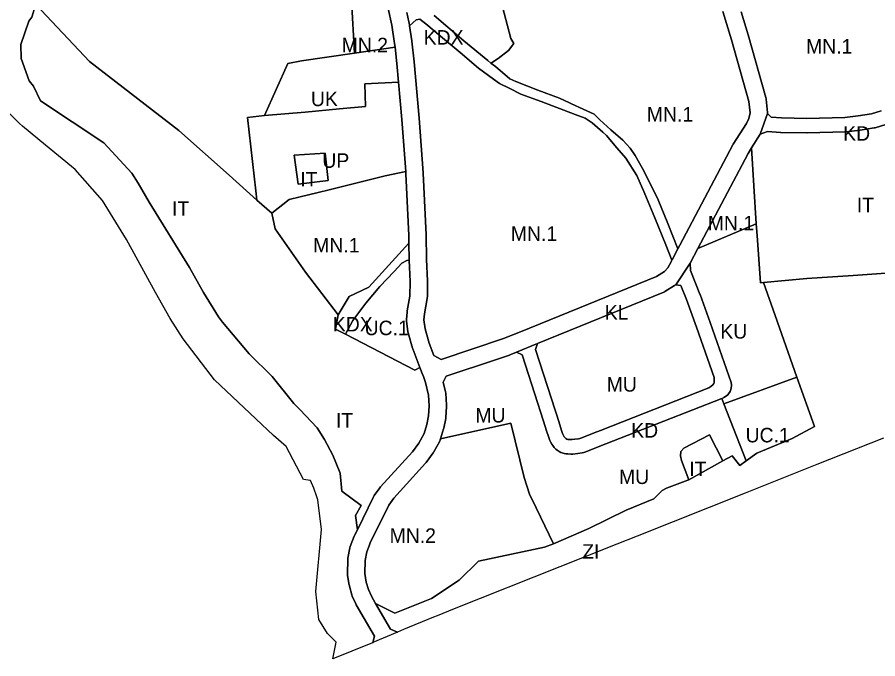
# Model space of a CAD drawing. Extents: x 7431767 to 7433133, y 5549450 to 5550702.
# Drawn here: x 7432225 to 7432819, y 5549450 to 5549893 of the extents above; entities that cross this region are included whole.
import ezdxf

# ---------------------------------------------------------------- set-up
doc = ezdxf.new("R2010")
doc.units = 0
doc.layers.add('linie_rozgraniczajace', color=7, linetype='Continuous')
doc.layers.add('oznaczenia_przeznaczen', color=7, linetype='Continuous')

msp = doc.modelspace()

# ---------------------------------------------------------------- linework, layer by layer
at = {"layer": 'linie_rozgraniczajace'}
for points in [[(7432557.4, 5549908.99), (7432565.41, 5549878.06), (7432567.36, 5549874.65), (7432563.8, 5549869.83), (7432556.62, 5549864.24), (7432552.14, 5549861.46), (7432551.68, 5549861.15), (7432549.45, 5549862.88), (7432532.98, 5549876.47), (7432512.5, 5549894.02)], [(7432711.61, 5549896.7), (7432717.56, 5549877.14), (7432729.67, 5549834.62), (7432730.42, 5549826.81), (7432729.64, 5549822.98), (7432727.85, 5549819.49), (7432718.76, 5549805.14), (7432718.65, 5549804.9), (7432718.53, 5549804.74), (7432681.99, 5549735.62), (7432680.66, 5549733.08), (7432673.64, 5549750.42), (7432667.12, 5549766.8), (7432659.94, 5549781.24), (7432656.21, 5549788.37), (7432651.18, 5549797.53), (7432647.66, 5549802.42), (7432642.59, 5549807.97), (7432634.3, 5549815.05), (7432626.88, 5549822.03), (7432622.88, 5549825.97), (7432617.72, 5549828.25), (7432615.3, 5549829.33), (7432607.27, 5549832.99), (7432605.87, 5549833.66), (7432599.04, 5549836.95), (7432584.12, 5549842.44), (7432568.93, 5549848.41), (7432564.81, 5549850.43), (7432554.78, 5549858.73), (7432551.68, 5549861.15), (7432552.14, 5549861.46), (7432556.62, 5549864.24), (7432563.8, 5549869.83), (7432567.36, 5549874.65), (7432565.41, 5549878.06), (7432557.4, 5549908.99)], [(7432455.58, 5549904.25), (7432457.52, 5549868.02), (7432421.02, 5549862.63), (7432411.67, 5549860.97), (7432395.56, 5549824.94), (7432383.73, 5549823.62), (7432389.41, 5549773.01), (7432390.29, 5549766.69), (7432371.05, 5549783.92), (7432336.34, 5549814.7), (7432274.77, 5549862.2), (7432237.84, 5549901.52)], [(7432237.84, 5549901.52), (7432274.77, 5549862.2), (7432336.34, 5549814.7), (7432371.05, 5549783.92), (7432390.29, 5549766.69), (7432400.61, 5549757.58), (7432402.86, 5549746.86), (7432423.86, 5549717), (7432446.24, 5549687.41), (7432444.54, 5549677.59), (7432451.31, 5549674.09), (7432499.26, 5549649.31), (7432502.63, 5549651.09), (7432504.59, 5549645.96), (7432504.82, 5549645.62), (7432506.45, 5549640.91), (7432508.56, 5549632.01), (7432509.11, 5549624.74), (7432508.63, 5549617.9), (7432507.41, 5549611.95), (7432505.51, 5549605.59), (7432501.9, 5549598.93), (7432497.55, 5549592.91), (7432475.54, 5549568.76), (7432475.12, 5549568.24), (7432471.24, 5549562.89), (7432470.98, 5549562.41), (7432470.72, 5549562.01), (7432459.54, 5549539.23), (7432458.32, 5549549.15), (7432462.08, 5549556.07), (7432448.76, 5549565.92), (7432447.6, 5549578.37), (7432442.66, 5549590.67), (7432436.94, 5549601.45), (7432431.82, 5549609.5), (7432419.86, 5549622.15), (7432415.69, 5549626.43), (7432400.74, 5549644.89), (7432384.84, 5549660.55), (7432366.47, 5549682.47), (7432363.79, 5549686.18), (7432353.38, 5549702.91), (7432343.77, 5549720.1), (7432315.99, 5549765.15), (7432308.26, 5549778.4), (7432304.07, 5549785.22), (7432284.58, 5549806.24), (7432240.93, 5549835.19), (7432236.06, 5549845.16), (7432233.16, 5549848.85), (7432227.68, 5549864.31), (7432227.29, 5549874.03), (7432232.98, 5549890.15), (7432235, 5549892.77), (7432237.51, 5549901.14)], [(7432237.51, 5549901.14), (7432235, 5549892.77), (7432232.98, 5549890.15), (7432227.29, 5549874.03), (7432227.68, 5549864.31), (7432233.16, 5549848.85), (7432236.06, 5549845.16), (7432240.93, 5549835.19), (7432284.58, 5549806.24), (7432304.07, 5549785.22), (7432308.26, 5549778.4), (7432315.99, 5549765.15), (7432343.77, 5549720.1), (7432353.38, 5549702.91), (7432363.79, 5549686.18), (7432366.47, 5549682.47), (7432384.84, 5549660.55), (7432400.74, 5549644.89), (7432415.69, 5549626.43), (7432419.86, 5549622.15), (7432431.82, 5549609.5), (7432436.94, 5549601.45), (7432442.66, 5549590.67), (7432447.6, 5549578.37), (7432448.76, 5549565.92), (7432462.08, 5549556.07), (7432458.32, 5549549.15), (7432459.54, 5549539.23)], [(7432520.6, 5549616.69), (7432520.52, 5549616.35), (7432520.48, 5549615.87), (7432519.12, 5549609.26), (7432518.98, 5549608.84), (7432516.94, 5549601.99), (7432516.8, 5549601.55), (7432516.72, 5549601.41), (7432516.69, 5549601.21), (7432516.35, 5549600.43), (7432512.28, 5549592.89), (7432512.04, 5549592.54), (7432511.87, 5549592.22), (7432507.07, 5549585.61), (7432506.65, 5549585.09), (7432484.65, 5549560.93), (7432481.24, 5549556.27), (7432468.47, 5549530.19), (7432467.65, 5549528.11), (7432466.04, 5549524), (7432464.88, 5549517.9), (7432464.76, 5549509.1), (7432465.72, 5549503.14), (7432467.12, 5549497.95), (7432469.19, 5549493.32), (7432472.08, 5549488.38), (7432482.46, 5549470.75), (7432487.23, 5549468.61), (7432470.24, 5549461.33), (7432471.43, 5549465.82), (7432458.7, 5549487.52), (7432458.39, 5549488.11), (7432455.95, 5549493.52), (7432455.67, 5549494.36), (7432454.05, 5549500.31), (7432454, 5549500.67), (7432453.93, 5549500.92), (7432452.81, 5549507.71), (7432452.75, 5549508.42), (7432452.77, 5549508.6), (7432452.74, 5549508.75), (7432452.9, 5549518.59), (7432452.95, 5549518.85), (7432452.98, 5549519.61), (7432454.35, 5549526.78), (7432454.63, 5549527.73), (7432457.4, 5549534.83), (7432457.57, 5549535.25), (7432459.54, 5549539.23), (7432470.72, 5549562.01), (7432470.98, 5549562.41), (7432471.24, 5549562.89), (7432475.12, 5549568.24), (7432475.54, 5549568.76), (7432497.55, 5549592.91), (7432501.9, 5549598.93), (7432505.51, 5549605.59), (7432507.41, 5549611.95), (7432508.63, 5549617.9), (7432509.11, 5549624.74), (7432508.56, 5549632.01), (7432506.45, 5549640.91), (7432504.82, 5549645.62), (7432504.59, 5549645.96), (7432502.63, 5549651.09), (7432497.73, 5549663.97), (7432497.55, 5549664.45), (7432494.52, 5549675.12), (7432494.43, 5549675.75), (7432494.33, 5549676.06), (7432493.51, 5549683.13), (7432493.53, 5549683.34), (7432493.46, 5549683.59), (7432493.47, 5549684.22), (7432493.82, 5549689.42), (7432493.87, 5549689.7), (7432493.91, 5549690.15), (7432495.81, 5549700.36), (7432495.93, 5549710.61), (7432495.34, 5549725.17), (7432495.33, 5549725.34), (7432495.14, 5549736.87), (7432495.05, 5549742.32), (7432493.05, 5549784.68), (7432492.92, 5549786.29), (7432490.18, 5549822.16), (7432487.94, 5549848.01), (7432486.83, 5549860.84), (7432485.5, 5549872.15), (7432485.17, 5549874.8), (7432483.35, 5549887.26), (7432480.75, 5549898.9)], [(7432493.66, 5549896.09), (7432495.11, 5549889.67), (7432495.15, 5549889.38), (7432495.18, 5549889.24), (7432495.53, 5549886.93), (7432497.08, 5549876.47), (7432497.08, 5549876.33), (7432498.75, 5549862.15), (7432498.76, 5549861.96), (7432502.12, 5549823.16), (7432505.02, 5549785.52), (7432505.03, 5549785.34), (7432507.04, 5549742.79), (7432507.05, 5549742.61), (7432507.33, 5549725.61), (7432507.92, 5549710.95), (7432507.9, 5549710.79), (7432507.94, 5549710.65), (7432507.82, 5549699.72), (7432507.76, 5549699.48), (7432507.7, 5549698.67), (7432505.75, 5549688.29), (7432505.48, 5549683.99), (7432506.2, 5549677.94), (7432509.01, 5549667.97), (7432512.3, 5549659.34), (7432517.28, 5549656.75), (7432560.45, 5549671.08), (7432572.18, 5549675.86), (7432665.85, 5549714.06), (7432671.41, 5549717.47), (7432673.71, 5549719.98), (7432675.89, 5549724.11), (7432676.21, 5549724.72), (7432676.47, 5549725.2), (7432676.59, 5549725.43), (7432680.66, 5549733.08), (7432681.99, 5549735.62), (7432718.53, 5549804.74), (7432718.65, 5549804.9), (7432718.76, 5549805.14), (7432727.85, 5549819.49), (7432729.64, 5549822.98), (7432730.42, 5549826.81), (7432729.67, 5549834.62), (7432717.56, 5549877.14), (7432711.61, 5549896.7)], [(7432512.5, 5549894.02), (7432532.98, 5549876.47), (7432549.45, 5549862.88), (7432551.68, 5549861.15), (7432554.78, 5549858.73), (7432564.81, 5549850.43), (7432568.93, 5549848.41), (7432584.12, 5549842.44), (7432599.04, 5549836.95), (7432605.87, 5549833.66), (7432607.27, 5549832.99), (7432615.3, 5549829.33), (7432617.72, 5549828.25), (7432622.88, 5549825.97), (7432626.88, 5549822.03), (7432634.3, 5549815.05), (7432642.59, 5549807.97), (7432647.66, 5549802.42), (7432651.18, 5549797.53), (7432656.21, 5549788.37), (7432659.94, 5549781.24), (7432667.12, 5549766.8), (7432673.64, 5549750.42), (7432680.66, 5549733.08), (7432676.59, 5549725.43), (7432676.47, 5549725.2), (7432672.38, 5549735.87), (7432664.78, 5549754.4), (7432657.92, 5549770.9), (7432652.27, 5549783.68), (7432644.66, 5549795.52), (7432638.48, 5549802.81), (7432631.45, 5549811.27), (7432628.89, 5549813.51), (7432621.53, 5549819.9), (7432616.58, 5549823.27), (7432609.78, 5549825.71), (7432586.43, 5549834.75), (7432572.19, 5549839.79), (7432564.68, 5549843.74), (7432557.66, 5549847.06), (7432553.51, 5549850.02), (7432543.19, 5549857.68), (7432530.37, 5549868.46), (7432516.96, 5549879.76), (7432506.77, 5549888.18), (7432502.54, 5549891.42), (7432500.15, 5549891.02), (7432495.53, 5549886.93), (7432495.18, 5549889.24), (7432495.15, 5549889.38), (7432495.11, 5549889.67), (7432493.66, 5549896.09)], [(7432724.22, 5549896.44), (7432729.06, 5549880.57), (7432741.35, 5549837.39), (7432741.47, 5549836.62), (7432741.55, 5549836.34), (7432742.45, 5549827.09), (7432742.43, 5549826.92), (7432742.5, 5549826.74), (7432742.48, 5549826.44), (7432737.37, 5549812.09), (7432731.37, 5549802.63), (7432729.02, 5549798.92), (7432694.32, 5549733.25), (7432689, 5549723.21), (7432679.13, 5549708.26), (7432678.4, 5549707.68), (7432671.72, 5549703.58), (7432671.11, 5549703.25), (7432670.95, 5549703.21), (7432583.74, 5549667.61), (7432569.4, 5549661.74), (7432568.88, 5549661.56), (7432564.82, 5549659.9), (7432564.42, 5549659.76), (7432554.73, 5549656.54), (7432520.75, 5549645.27), (7432518.73, 5549641.12), (7432520.35, 5549634.32), (7432520.45, 5549633.51), (7432520.49, 5549633.38), (7432521.1, 5549625.2), (7432521.11, 5549625), (7432521.1, 5549624.36), (7432520.6, 5549616.69)], [(7432820.96, 5549828.3), (7432814.2, 5549826.27), (7432804.93, 5549824.88), (7432795.76, 5549823.69), (7432769.67, 5549823.05), (7432752.11, 5549823.38), (7432744.96, 5549823.9), (7432742.48, 5549826.44), (7432742.5, 5549826.74), (7432742.43, 5549826.92), (7432742.45, 5549827.09), (7432741.55, 5549836.34), (7432741.47, 5549836.62), (7432741.35, 5549837.39), (7432729.06, 5549880.57), (7432724.22, 5549896.44)], [(7432459.54, 5549539.23), (7432457.57, 5549535.25), (7432457.4, 5549534.83), (7432454.63, 5549527.73), (7432454.35, 5549526.78), (7432452.98, 5549519.61), (7432452.95, 5549518.85), (7432452.9, 5549518.59), (7432452.74, 5549508.75), (7432452.77, 5549508.6), (7432452.75, 5549508.42), (7432452.81, 5549507.71), (7432453.93, 5549500.92), (7432454, 5549500.67), (7432454.05, 5549500.31), (7432455.67, 5549494.36), (7432455.95, 5549493.52), (7432458.39, 5549488.11), (7432458.7, 5549487.52), (7432471.43, 5549465.82), (7432470.24, 5549461.33), (7432470.11, 5549461.28), (7432468.73, 5549460.72), (7432442.67, 5549450.2), (7432444.92, 5549461.75), (7432438.86, 5549467.66), (7432433, 5549477.22), (7432430.83, 5549496.73), (7432434.82, 5549539.41), (7432432.18, 5549559.76), (7432431.5, 5549561.94), (7432429.57, 5549567.98), (7432427.29, 5549573.19), (7432422.48, 5549573.83), (7432410.51, 5549596.71), (7432401.8, 5549604.16), (7432389.5, 5549615.83), (7432360.89, 5549642.74), (7432339.45, 5549670.99), (7432330.5, 5549685.08), (7432320.23, 5549702.93), (7432300.33, 5549739.45), (7432283.67, 5549766.3), (7432264.84, 5549787.87), (7432244.52, 5549804.54), (7432228.45, 5549817.7), (7432226.52, 5549819.61), (7432213.55, 5549832.48)], [(7432824.07, 5549818.8), (7432816.75, 5549816.59), (7432816.34, 5549816.53), (7432816.04, 5549816.44), (7432806.27, 5549814.97), (7432796.79, 5549813.74), (7432796.26, 5549813.7), (7432769.79, 5549813.05), (7432769.61, 5549813.05), (7432751.73, 5549813.39), (7432751.52, 5549813.4), (7432742.54, 5549814.05), (7432737.37, 5549812.09), (7432742.48, 5549826.44), (7432744.96, 5549823.9), (7432752.11, 5549823.38), (7432769.67, 5549823.05), (7432795.76, 5549823.69), (7432804.93, 5549824.88), (7432814.2, 5549826.27), (7432820.96, 5549828.3)], [(7432881.66, 5549720.43), (7432801.62, 5549714.66), (7432769.59, 5549712.51), (7432739.68, 5549709.72), (7432737.53, 5549709.52), (7432735.23, 5549742.26), (7432734.72, 5549750.3), (7432731.37, 5549802.63), (7432737.37, 5549812.09), (7432742.54, 5549814.05), (7432751.52, 5549813.4), (7432751.73, 5549813.39), (7432769.61, 5549813.05), (7432769.79, 5549813.05), (7432796.26, 5549813.7), (7432796.79, 5549813.74), (7432806.27, 5549814.97), (7432816.04, 5549816.44), (7432816.34, 5549816.53), (7432816.75, 5549816.59), (7432824.07, 5549818.8)], [(7432822.5, 5549602.39), (7432776.42, 5549584.13), (7432753.5, 5549575), (7432727.06, 5549564.47), (7432652.55, 5549534.82), (7432638.61, 5549529.27), (7432599.18, 5549513.57), (7432526.3, 5549484.58), (7432514.58, 5549479.9), (7432512.15, 5549478.93), (7432491.29, 5549470.32), (7432487.23, 5549468.61), (7432482.46, 5549470.75), (7432472.08, 5549488.38), (7432485.42, 5549481.65), (7432510.69, 5549491.81), (7432529.85, 5549504.37), (7432543.07, 5549517.62), (7432588.56, 5549527.28), (7432594.84, 5549529.61), (7432619.31, 5549540.13), (7432644.85, 5549552.82), (7432664.14, 5549560.59), (7432669.85, 5549566.33), (7432672.72, 5549567.93), (7432687.54, 5549573.4), (7432688.22, 5549573.78), (7432711.64, 5549586.78), (7432718, 5549590.31), (7432723.47, 5549583.55), (7432727.78, 5549586.75), (7432734.98, 5549592.06), (7432741.65, 5549594.87), (7432759.55, 5549602.17), (7432774.79, 5549610.41), (7432762.74, 5549644.59), (7432747.76, 5549687.05), (7432739.68, 5549709.72), (7432769.59, 5549712.51), (7432801.62, 5549714.66), (7432881.66, 5549720.43)]]:
    msp.add_lwpolyline(points, dxfattribs=at)
for points in [[(7432457.52, 5549868.02), (7432455.58, 5549904.25), (7432479.4, 5549904.39), (7432480.75, 5549898.9), (7432483.35, 5549887.26), (7432485.17, 5549874.8), (7432485.5, 5549872.15)], [(7432495.53, 5549886.93), (7432500.15, 5549891.02), (7432502.54, 5549891.42), (7432506.77, 5549888.18), (7432516.96, 5549879.76), (7432530.37, 5549868.46), (7432543.19, 5549857.68), (7432553.51, 5549850.02), (7432557.66, 5549847.06), (7432564.68, 5549843.74), (7432572.19, 5549839.79), (7432586.43, 5549834.75), (7432609.78, 5549825.71), (7432616.58, 5549823.27), (7432621.53, 5549819.9), (7432628.89, 5549813.51), (7432631.45, 5549811.27), (7432638.48, 5549802.81), (7432644.66, 5549795.52), (7432652.27, 5549783.68), (7432657.92, 5549770.9), (7432664.78, 5549754.4), (7432672.38, 5549735.87), (7432676.47, 5549725.2), (7432676.21, 5549724.72), (7432675.89, 5549724.11), (7432673.71, 5549719.98), (7432671.41, 5549717.47), (7432665.85, 5549714.06), (7432572.18, 5549675.86), (7432560.45, 5549671.08), (7432517.28, 5549656.75), (7432512.3, 5549659.34), (7432509.01, 5549667.97), (7432506.2, 5549677.94), (7432505.48, 5549683.99), (7432505.75, 5549688.29), (7432507.7, 5549698.67), (7432507.76, 5549699.48), (7432507.82, 5549699.72), (7432507.94, 5549710.65), (7432507.9, 5549710.79), (7432507.92, 5549710.95), (7432507.33, 5549725.61), (7432507.05, 5549742.61), (7432507.04, 5549742.79), (7432505.03, 5549785.34), (7432505.02, 5549785.52), (7432502.12, 5549823.16), (7432498.76, 5549861.96), (7432498.75, 5549862.15), (7432497.08, 5549876.33), (7432497.08, 5549876.47)], [(7432485.5, 5549872.15), (7432486.83, 5549860.84), (7432487.94, 5549848.01), (7432464.66, 5549846.77), (7432465.11, 5549831.17), (7432447.19, 5549829.58), (7432423.55, 5549827.37), (7432395.56, 5549824.94), (7432411.67, 5549860.97), (7432421.02, 5549862.63), (7432457.52, 5549868.02)], [(7432487.94, 5549848.01), (7432490.18, 5549822.16), (7432492.92, 5549786.29), (7432478.78, 5549783.41), (7432440.17, 5549773.73), (7432432.46, 5549771.79), (7432420.1, 5549768.91), (7432412.6, 5549767.17), (7432400.61, 5549757.58), (7432390.29, 5549766.69), (7432389.41, 5549773.01), (7432383.73, 5549823.62), (7432395.56, 5549824.94), (7432423.55, 5549827.37), (7432447.19, 5549829.58), (7432465.11, 5549831.17), (7432464.66, 5549846.77)], [(7432731.37, 5549802.63), (7432734.72, 5549750.3), (7432694.32, 5549733.25), (7432729.02, 5549798.92)], [(7432418.81, 5549777.63), (7432439.44, 5549780.1), (7432437.3, 5549799), (7432415.83, 5549797.74)], [(7432418.81, 5549777.63), (7432415.83, 5549797.74), (7432437.3, 5549799), (7432439.44, 5549780.1)], [(7432492.92, 5549786.29), (7432493.05, 5549784.68), (7432495.05, 5549742.32), (7432495.14, 5549736.87), (7432467.51, 5549706.49), (7432453.79, 5549700.21), (7432446.24, 5549687.41), (7432423.86, 5549717), (7432402.86, 5549746.86), (7432400.61, 5549757.58), (7432412.6, 5549767.17), (7432420.1, 5549768.91), (7432432.46, 5549771.79), (7432440.17, 5549773.73), (7432478.78, 5549783.41)], [(7432734.72, 5549750.3), (7432735.23, 5549742.26), (7432737.53, 5549709.52), (7432739.68, 5549709.72), (7432747.76, 5549687.05), (7432762.74, 5549644.59), (7432712.43, 5549626.06), (7432710.96, 5549629.84), (7432712.1, 5549630.3), (7432712.22, 5549630.37), (7432712.37, 5549630.41), (7432713.44, 5549631.07), (7432715.08, 5549632.41), (7432715.59, 5549632.9), (7432716.59, 5549634.5), (7432717.18, 5549636.01), (7432717.45, 5549637.17), (7432717.62, 5549638.45), (7432717.64, 5549639.27), (7432717.37, 5549640.72), (7432702.89, 5549682.28), (7432695.95, 5549701.54), (7432695.88, 5549701.74), (7432689.24, 5549717.98), (7432689, 5549723.21), (7432694.32, 5549733.25)], [(7432495.14, 5549736.87), (7432495.33, 5549725.34), (7432495.34, 5549725.17), (7432493.72, 5549725.04), (7432490.32, 5549723.22), (7432484.99, 5549717.44), (7432474.99, 5549707.05), (7432465.39, 5549695.62), (7432456.4, 5549683.69), (7432451.31, 5549674.09), (7432444.54, 5549677.59), (7432446.24, 5549687.41), (7432453.79, 5549700.21), (7432467.51, 5549706.49)], [(7432495.34, 5549725.17), (7432495.93, 5549710.61), (7432495.81, 5549700.36), (7432493.91, 5549690.15), (7432493.87, 5549689.7), (7432493.82, 5549689.42), (7432493.47, 5549684.22), (7432493.46, 5549683.59), (7432493.53, 5549683.34), (7432493.51, 5549683.13), (7432494.33, 5549676.06), (7432494.43, 5549675.75), (7432494.52, 5549675.12), (7432497.55, 5549664.45), (7432497.73, 5549663.97), (7432502.63, 5549651.09), (7432499.26, 5549649.31), (7432451.31, 5549674.09), (7432456.4, 5549683.69), (7432465.39, 5549695.62), (7432474.99, 5549707.05), (7432484.99, 5549717.44), (7432490.32, 5549723.22), (7432493.72, 5549725.04)], [(7432689, 5549723.21), (7432689.24, 5549717.98), (7432695.88, 5549701.74), (7432695.95, 5549701.54), (7432702.89, 5549682.28), (7432717.37, 5549640.72), (7432717.64, 5549639.27), (7432717.62, 5549638.45), (7432717.45, 5549637.17), (7432717.18, 5549636.01), (7432716.59, 5549634.5), (7432715.59, 5549632.9), (7432715.08, 5549632.41), (7432713.44, 5549631.07), (7432712.37, 5549630.41), (7432712.22, 5549630.37), (7432712.1, 5549630.3), (7432710.96, 5549629.84), (7432630.89, 5549598.44), (7432622.24, 5549595.04), (7432617.13, 5549593.05), (7432615.71, 5549592.5), (7432614.72, 5549592.24), (7432611.64, 5549591.84), (7432608.28, 5549591.46), (7432606.78, 5549591.39), (7432604.65, 5549591.49), (7432603.24, 5549591.6), (7432602.1, 5549591.85), (7432600.84, 5549592.24), (7432599.98, 5549592.56), (7432598.7, 5549593.21), (7432597.26, 5549594.08), (7432596.39, 5549594.74), (7432595.24, 5549596.06), (7432594.26, 5549597.25), (7432593.59, 5549598.23), (7432592.74, 5549599.89), (7432592.26, 5549600.84), (7432591.31, 5549603.5), (7432590.06, 5549607.4), (7432587.91, 5549614.07), (7432585.58, 5549621.35), (7432584.01, 5549626.24), (7432573.11, 5549659.83), (7432569.4, 5549661.74), (7432583.74, 5549667.61), (7432582.33, 5549663.67), (7432593.44, 5549629.66), (7432595.8, 5549622.32), (7432597.06, 5549618.36), (7432599.24, 5549611.53), (7432600.46, 5549607.66), (7432601.13, 5549605.74), (7432601.73, 5549604.29), (7432602.23, 5549603.3), (7432602.89, 5549602.54), (7432603.32, 5549602.12), (7432603.99, 5549601.73), (7432604.71, 5549601.52), (7432605.5, 5549601.44), (7432606.57, 5549601.38), (7432607.75, 5549601.48), (7432609.49, 5549601.66), (7432612.08, 5549602.01), (7432612.98, 5549602.14), (7432614.49, 5549602.75), (7432622.86, 5549606.03), (7432627.14, 5549607.7), (7432702.06, 5549637.1), (7432703.46, 5549638.06), (7432704.67, 5549639.11), (7432705.38, 5549640.2), (7432705.59, 5549641.15), (7432705.71, 5549642.9), (7432705.56, 5549644.25), (7432693.45, 5549678.96), (7432686.58, 5549698.05), (7432682.59, 5549707.76), (7432679.13, 5549708.26)], [(7432679.13, 5549708.26), (7432682.59, 5549707.76), (7432686.58, 5549698.05), (7432693.45, 5549678.96), (7432705.56, 5549644.25), (7432705.71, 5549642.9), (7432705.59, 5549641.15), (7432705.38, 5549640.2), (7432704.67, 5549639.11), (7432703.46, 5549638.06), (7432702.06, 5549637.1), (7432627.14, 5549607.7), (7432622.86, 5549606.03), (7432614.49, 5549602.75), (7432612.98, 5549602.14), (7432612.08, 5549602.01), (7432609.49, 5549601.66), (7432607.75, 5549601.48), (7432606.57, 5549601.38), (7432605.5, 5549601.44), (7432604.71, 5549601.52), (7432603.99, 5549601.73), (7432603.32, 5549602.12), (7432602.89, 5549602.54), (7432602.23, 5549603.3), (7432601.73, 5549604.29), (7432601.13, 5549605.74), (7432600.46, 5549607.66), (7432599.24, 5549611.53), (7432597.06, 5549618.36), (7432595.8, 5549622.32), (7432593.44, 5549629.66), (7432582.33, 5549663.67), (7432583.74, 5549667.61), (7432670.95, 5549703.21), (7432671.11, 5549703.25), (7432671.72, 5549703.58), (7432678.4, 5549707.68)], [(7432569.4, 5549661.74), (7432573.11, 5549659.83), (7432584.01, 5549626.24), (7432585.58, 5549621.35), (7432587.91, 5549614.07), (7432590.06, 5549607.4), (7432591.31, 5549603.5), (7432592.26, 5549600.84), (7432592.74, 5549599.89), (7432593.59, 5549598.23), (7432594.26, 5549597.25), (7432595.24, 5549596.06), (7432596.39, 5549594.74), (7432597.26, 5549594.08), (7432598.7, 5549593.21), (7432599.98, 5549592.56), (7432600.84, 5549592.24), (7432602.1, 5549591.85), (7432603.24, 5549591.6), (7432604.65, 5549591.49), (7432606.78, 5549591.39), (7432608.28, 5549591.46), (7432611.64, 5549591.84), (7432614.72, 5549592.24), (7432615.71, 5549592.5), (7432617.13, 5549593.05), (7432622.24, 5549595.04), (7432630.89, 5549598.44), (7432710.96, 5549629.84), (7432712.43, 5549626.06), (7432727.78, 5549586.75), (7432723.47, 5549583.55), (7432718, 5549590.31), (7432711.64, 5549586.78), (7432702.34, 5549604.81), (7432684.74, 5549595.53), (7432682.61, 5549593.23), (7432682.45, 5549590.18), (7432683.15, 5549586.89), (7432688.22, 5549573.78), (7432687.54, 5549573.4), (7432672.72, 5549567.93), (7432669.85, 5549566.33), (7432664.14, 5549560.59), (7432644.85, 5549552.82), (7432619.31, 5549540.13), (7432594.84, 5549529.61), (7432582.83, 5549554.33), (7432578.26, 5549563.76), (7432574.6, 5549575.26), (7432565.45, 5549612.74), (7432516.94, 5549601.99), (7432518.98, 5549608.84), (7432519.12, 5549609.26), (7432520.48, 5549615.87), (7432520.52, 5549616.35), (7432520.6, 5549616.69), (7432521.1, 5549624.36), (7432521.11, 5549625), (7432521.1, 5549625.2), (7432520.49, 5549633.38), (7432520.45, 5549633.51), (7432520.35, 5549634.32), (7432518.73, 5549641.12), (7432520.75, 5549645.27), (7432554.73, 5549656.54), (7432564.42, 5549659.76), (7432564.82, 5549659.9), (7432568.88, 5549661.56)], [(7432762.74, 5549644.59), (7432774.79, 5549610.41), (7432759.55, 5549602.17), (7432741.65, 5549594.87), (7432734.98, 5549592.06), (7432727.78, 5549586.75), (7432712.43, 5549626.06)], [(7432516.94, 5549601.99), (7432565.45, 5549612.74), (7432574.6, 5549575.26), (7432578.26, 5549563.76), (7432582.83, 5549554.33), (7432594.84, 5549529.61), (7432588.56, 5549527.28), (7432543.07, 5549517.62), (7432529.85, 5549504.37), (7432510.69, 5549491.81), (7432485.42, 5549481.65), (7432472.08, 5549488.38), (7432469.19, 5549493.32), (7432467.12, 5549497.95), (7432465.72, 5549503.14), (7432464.76, 5549509.1), (7432464.88, 5549517.9), (7432466.04, 5549524), (7432467.65, 5549528.11), (7432468.47, 5549530.19), (7432481.24, 5549556.27), (7432484.65, 5549560.93), (7432506.65, 5549585.09), (7432507.07, 5549585.61), (7432511.87, 5549592.22), (7432512.04, 5549592.54), (7432512.28, 5549592.89), (7432516.35, 5549600.43), (7432516.69, 5549601.21), (7432516.72, 5549601.41), (7432516.8, 5549601.55)], [(7432688.22, 5549573.78), (7432683.15, 5549586.89), (7432682.45, 5549590.18), (7432682.61, 5549593.23), (7432684.74, 5549595.53), (7432702.34, 5549604.81), (7432711.64, 5549586.78)]]:
    msp.add_lwpolyline(points, close=True, dxfattribs=at)

# ---------------------------------------------------------------- texts
at = {"layer": 'oznaczenia_przeznaczen'}
for s, p in [('KDX', (7432505.27, 5549873.92)), ('MN.2', (7432448.7, 5549868.66)), ('MN.1', (7432769.06, 5549867.76)), ('UK', (7432427.51, 5549831.49)), ('MN.1', (7432659.24, 5549820.88)), ('KD', (7432794.66, 5549807.64)), ('UP', (7432435.37, 5549788.94)), ('IT', (7432420.15, 5549776.05)), ('IT', (7432331.68, 5549755.82)), ('IT', (7432804, 5549758.32)), ('MN.1', (7432701.27, 5549745.75)), ('MN.1', (7432565.41, 5549738.55)), ('MN.1', (7432429.07, 5549730.52)), ('KL', (7432630.19, 5549684.23)), ('KDX', (7432442.62, 5549676.03)), ('UC.1', (7432464.52, 5549673.46)), ('KU', (7432709.88, 5549671.1)), ('MU', (7432631.53, 5549634.51)), ('MU', (7432540.93, 5549613.21)), ('IT', (7432444.79, 5549609.73)), ('KD', (7432648.43, 5549602.77)), ('UC.1', (7432727.33, 5549599.51)), ('IT', (7432688.53, 5549576.21)), ('MU', (7432640.02, 5549570.78)), ('MN.2', (7432481.78, 5549530.18)), ('ZI', (7432614.58, 5549519.24))]:
    msp.add_text(s, height=10, dxfattribs=at).set_placement(p)

doc.saveas('drawing.dxf')
